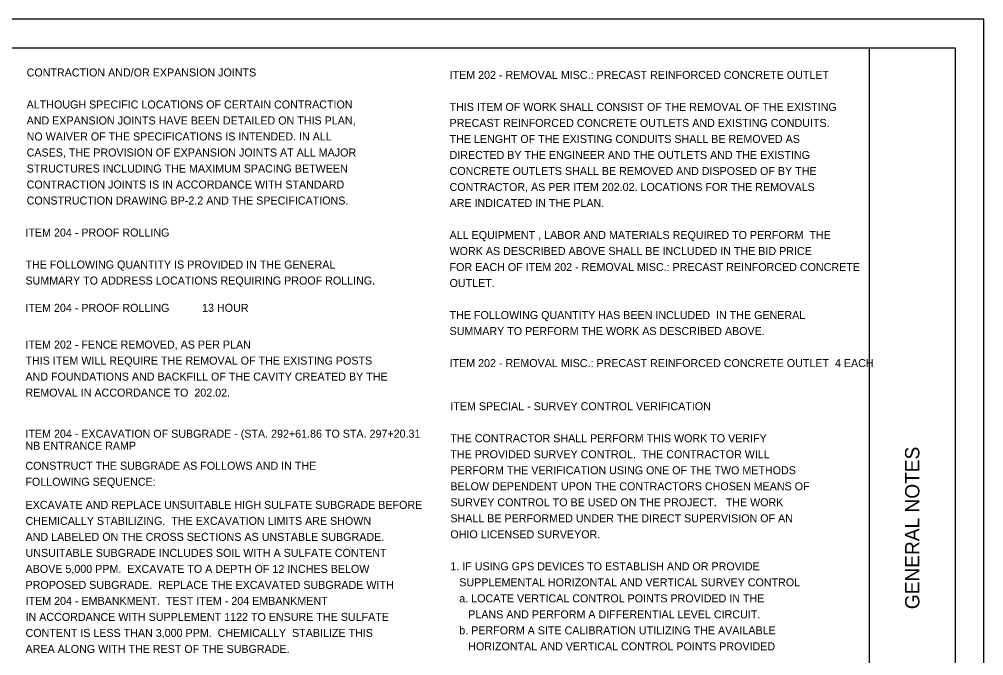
# Model space of a CAD drawing. Extents: x 0 to 34, y 0 to 22.
# Drawn here: x 17.13 to 34, y 10.87 to 22 of the extents above; entities that cross this region are included whole.
import ezdxf

# ---------------------------------------------------------------- set-up
doc = ezdxf.new("R2010")
doc.units = 0
for name, color, linetype in [('SH_Border', 7, 'Continuous'), ('SH_Cut_Line', 7, 'Continuous'), ('SH_Data', 7, 'Continuous'), ('SH_Text', 7, 'Continuous')]:
    doc.layers.add(name, color=color, linetype=linetype)

msp = doc.modelspace()

# ---------------------------------------------------------------- linework, layer by layer
at = {"layer": 'SH_Border'}
msp.add_line((32, 0.5), (32, 21.5), dxfattribs=at)
msp.add_lwpolyline([(1.5, 21.5), (33.5, 21.5), (33.5, 0.5), (1.5, 0.5)], close=True, dxfattribs=at)
at = {"layer": 'SH_Cut_Line'}
msp.add_lwpolyline([(0, 0), (34, 0), (34, 22), (0, 22)], close=True, dxfattribs=at)

# ---------------------------------------------------------------- texts
at = {"layer": 'SH_Data'}
msp.add_text('GENERAL NOTES', height=0.25, rotation=90, dxfattribs=at).set_placement((32.875, 11.682))
at = {"layer": 'SH_Text'}
for s, p in [('CONTRACTION AND/OR EXPANSION JOINTS', (17.261, 21)), ('ITEM 202 - REMOVAL MISC.: PRECAST REINFORCED CONCRETE OUTLET', (24.658, 20.957)), ('ALTHOUGH SPECIFIC LOCATIONS OF CERTAIN CONTRACTION', (17.261, 20.44)), ('THIS ITEM OF WORK SHALL CONSIST OF THE REMOVAL OF THE EXISTING', (24.658, 20.397)), ('AND EXPANSION JOINTS HAVE BEEN DETAILED ON THIS PLAN,', (17.261, 20.16)), ('PRECAST REINFORCED CONCRETE OUTLETS AND EXISTING CONDUITS. ', (24.658, 20.117)), ('NO WAIVER OF THE SPECIFICATIONS IS INTENDED. IN ALL', (17.261, 19.88)), ('THE LENGHT OF THE EXISTING CONDUITS SHALL BE REMOVED AS ', (24.658, 19.837)), ('CASES, THE PROVISION OF EXPANSION JOINTS AT ALL MAJOR', (17.261, 19.6)), ('DIRECTED BY THE ENGINEER AND THE OUTLETS AND THE EXISTING ', (24.658, 19.557)), ('STRUCTURES INCLUDING THE MAXIMUM SPACING BETWEEN', (17.261, 19.32)), ('CONCRETE OUTLETS SHALL BE REMOVED AND DISPOSED OF BY THE ', (24.658, 19.277)), ('CONTRACTION JOINTS IS IN ACCORDANCE WITH STANDARD', (17.261, 19.04)), ('CONTRACTOR, AS PER ITEM 202.02. LOCATIONS FOR THE REMOVALS ', (24.658, 18.997)), ('CONSTRUCTION DRAWING BP-2.2 AND THE SPECIFICATIONS.', (17.261, 18.76)), ('ARE INDICATED IN THE PLAN.  ', (24.658, 18.717)), ('ITEM 204 - PROOF ROLLING', (17.24, 18.2)), ('ALL EQUIPMENT , LABOR AND MATERIALS REQUIRED TO PERFORM  THE', (24.658, 18.157)), ('WORK AS DESCRIBED ABOVE SHALL BE INCLUDED IN THE BID PRICE', (24.658, 17.877)), ('THE FOLLOWING QUANTITY IS PROVIDED IN THE GENERAL', (17.24, 17.64)), ('FOR EACH OF ITEM 202 - REMOVAL MISC.: PRECAST REINFORCED CONCRETE ', (24.658, 17.597)), ('SUMMARY TO ADDRESS LOCATIONS REQUIRING PROOF ROLLING.', (17.24, 17.36)), ('OUTLET.', (24.658, 17.317)), ('ITEM 204 - PROOF ROLLING           13 HOUR', (17.24, 16.883)), ('THE FOLLOWING QUANTITY HAS BEEN INCLUDED  IN THE GENERAL ', (24.658, 16.757)), ('SUMMARY TO PERFORM THE WORK AS DESCRIBED ABOVE.', (24.658, 16.477)), ('ITEM 202 - FENCE REMOVED, AS PER PLAN', (17.24, 16.24)), ('THIS ITEM WILL REQUIRE THE REMOVAL OF THE EXISTING POSTS ', (17.24, 15.96)), ('ITEM 202 - REMOVAL MISC.: PRECAST REINFORCED CONCRETE OUTLET  4 EACH', (24.658, 15.917)), ('AND FOUNDATIONS AND BACKFILL OF THE CAVITY CREATED BY THE ', (17.24, 15.68)), ('REMOVAL IN ACCORDANCE TO  202.02.', (17.24, 15.4)), ('ITEM SPECIAL - SURVEY CONTROL VERIFICATION', (24.672, 15.162)), ('ITEM 204 - EXCAVATION OF SUBGRADE - (STA. 292+61.86 TO STA. 297+20.31', (17.24, 14.681)), ('THE CONTRACTOR SHALL PERFORM THIS WORK TO VERIFY', (24.672, 14.602)), ('NB ENTRANCE RAMP', (17.24, 14.471)), ('THE PROVIDED SURVEY CONTROL.  THE CONTRACTOR WILL', (24.672, 14.322)), ('CONSTRUCT THE SUBGRADE AS FOLLOWS AND IN THE', (17.24, 14.121)), ('PERFORM THE VERIFICATION USING ONE OF THE TWO METHODS', (24.672, 14.042)), ('FOLLOWING SEQUENCE:', (17.24, 13.841)), ('BELOW DEPENDENT UPON THE CONTRACTORS CHOSEN MEANS OF', (24.672, 13.762)), ('EXCAVATE AND REPLACE UNSUITABLE HIGH SULFATE SUBGRADE BEFORE', (17.242, 13.437)), ('SURVEY CONTROL TO BE USED ON THE PROJECT.   THE WORK', (24.672, 13.482)), ('SHALL BE PERFORMED UNDER THE DIRECT SUPERVISION OF AN', (24.672, 13.202)), ('CHEMICALLY STABILIZING.  THE EXCAVATION LIMITS ARE SHOWN', (17.242, 13.157)), ('AND LABELED ON THE CROSS SECTIONS AS UNSTABLE SUBGRADE. ', (17.242, 12.877)), ('OHIO LICENSED SURVEYOR.', (24.672, 12.922)), ('UNSUITABLE SUBGRADE INCLUDES SOIL WITH A SULFATE CONTENT', (17.242, 12.597)), ('1. IF USING GPS DEVICES TO ESTABLISH AND OR PROVIDE', (24.672, 12.362)), ('ABOVE 5,000 PPM.  EXCAVATE TO A DEPTH OF 12 INCHES BELOW', (17.242, 12.317)), ('PROPOSED SUBGRADE.  REPLACE THE EXCAVATED SUBGRADE WITH', (17.242, 12.037)), ('   SUPPLEMENTAL HORIZONTAL AND VERTICAL SURVEY CONTROL', (24.672, 12.082)), ('ITEM 204 - EMBANKMENT.  TEST ITEM - 204 EMBANKMENT', (17.242, 11.757)), ('   a. LOCATE VERTICAL CONTROL POINTS PROVIDED IN THE', (24.672, 11.802)), ('      PLANS AND PERFORM A DIFFERENTIAL LEVEL CIRCUIT.', (24.672, 11.522)), ('IN ACCORDANCE WITH SUPPLEMENT 1122 TO ENSURE THE SULFATE', (17.242, 11.477)), ('CONTENT IS LESS THAN 3,000 PPM.  CHEMICALLY  STABILIZE THIS', (17.242, 11.197)), ('   b. PERFORM A SITE CALIBRATION UTILIZING THE AVAILABLE', (24.672, 11.242)), ('AREA ALONG WITH THE REST OF THE SUBGRADE.', (17.242, 10.917)), ('      HORIZONTAL AND VERTICAL CONTROL POINTS PROVIDED', (24.672, 10.962))]:
    msp.add_text(s, height=0.14, dxfattribs=at).set_placement(p)

doc.saveas('drawing.dxf')
